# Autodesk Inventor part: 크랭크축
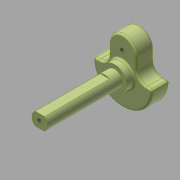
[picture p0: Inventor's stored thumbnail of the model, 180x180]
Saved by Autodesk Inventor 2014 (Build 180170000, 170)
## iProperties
Created: 2018-01
Part Number: 크랭크축
Material: 강철, 탄소
Document SubType Name: Modeling
Designer: mduedu
Density: 7.87 g/cm^3
Appearance: 아연 크롬산색 2
Mass: 57.3416 g
Surface Area: 32.1344 cm^2
Volume: 7.2861 cm^3
Author: mduedu
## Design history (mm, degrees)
sketch "스케치1"
  geometry: L1 (-15, 0)-(15, 0); L2 (-7, 0)-(7, 0); L3 (7, 0)-(7, 10); L4 (-7, 10)-(-7, 0); A1 r 15 centre (0, 0) between (-15, 0) and (15, 0); A2 r 7 centre (0, 10) between (7, 10) and (-7, 10); 3 further points
  constraints: 8 end point, 4 point on circle, 3 coincident, 2 centre point, 2 horizontal, 2 midpoint, 2 tangent, 1 parallel, 1 perpendicular, 1 point on line
  dimensions: "d0" = 30 diameter of A1; "d1" = 17 dimension on A2 L1; "d2" = 7 radius of A2
extrude "돌출1" new body sketch "스케치1" distance "d4" = 9; taper "d5" = 0 deg
sketch "스케치2"
  geometry: C1 r 6 at (0, 0); 1 further point
  constraints: 1 centre point, 1 coincident
  dimensions: "d6" = 12 diameter of C1
extrude "돌출2" join sketch "스케치2" distance "d7" = 4; taper "d8" = 0 deg
sketch "스케치3"
  geometry: C1 r 4 at (0, 0); 1 further point
  constraints: 1 centre point, 1 coincident
  dimensions: "d9" = 8 diameter of C1
extrude "돌출3" join sketch "스케치3" distance "d10" = 38; taper "d11" = 0 deg
sketch "스케치4"
  geometry: L1 (-2.332, 3.25)-(2.332, 3.25); L2 (-2.332, -3.25)-(2.332, -3.25); A1 r 4 centre (0, 0) between (-2.332, 3.25) and (2.332, 3.25) reference; A2 r 4 centre (0, 0) between (2.332, 3.25) and (-2.332, 3.25); A3 r 4 centre (0, 0) between (-2.332, -3.25) and (2.332, -3.25); 1 further point
  constraints: 8 point on circle, 4 end point, 2 centre point, 2 coincident, 2 parallel, 1 horizontal
  dimensions: "d12" = 6.5 distance between parallel lines of L2 L1
extrude "돌출4" cut sketch "스케치4" distance "d13" = 33; taper "d14" = 0 deg
fillet "모깎기1" dims "d15" = 5
fillet "모깎기2" dims "d16" = 1
fillet "모깎기3" dims "d17" = 1
fillet "모깎기4" dims "d18" = 1
sketch "스케치5"
  geometry: 1 further point
  constraints: 1 other
hole "구멍1" sketch "스케치5" at (0, 10) diameter "d19" = 2.459; stored, may be unused: countersink angle "d23" = 90 deg, drill point angle "d25" = 120 deg; dims "d20" = 10, "d21" = 4, "d22" = 2, "d24" = 11.5
sketch "스케치6"
  geometry: 1 further point
  constraints: 1 other
hole "구멍2" sketch "스케치6" at (0, 0) diameter "d26" = 2.459; stored, may be unused: countersink angle "d30" = 90 deg, drill point angle "d32" = 120 deg; dims "d27" = 12.7, "d28" = 4, "d29" = 2, "d31" = 14.2
node "솔리드1"
node "투영된 루프1"
